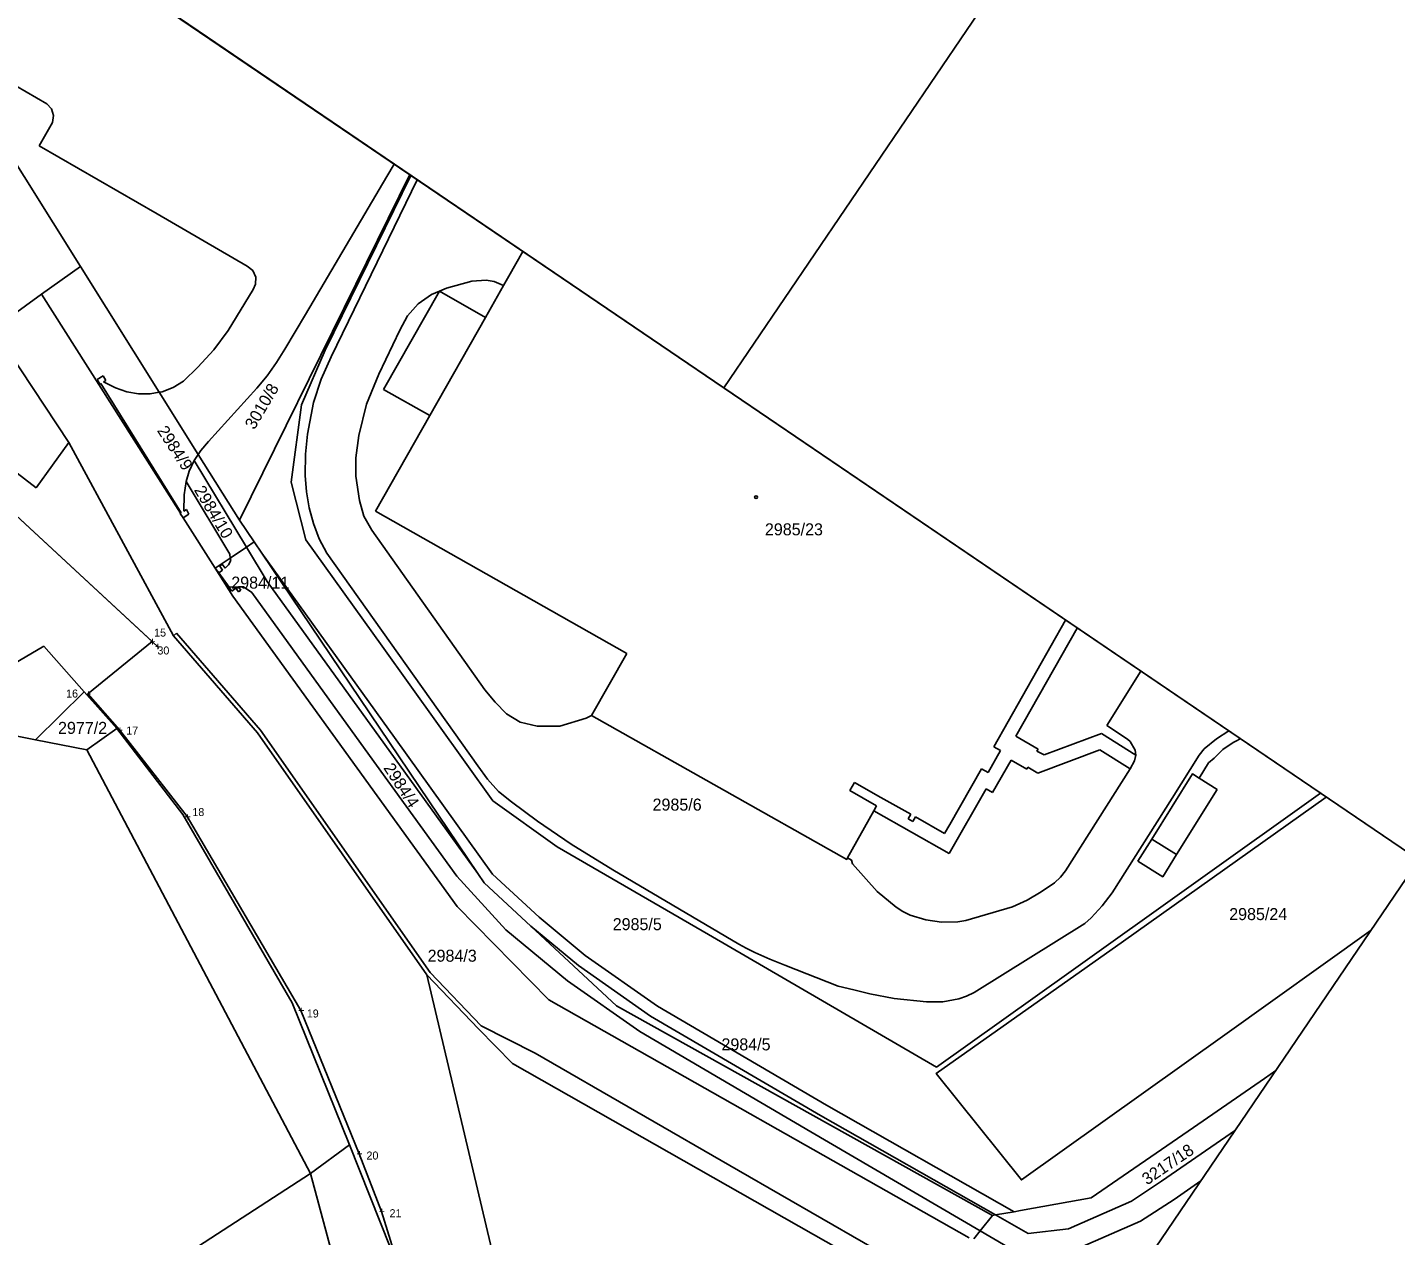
# Model space of a CAD drawing. Extents: x -620450 to -619936, y -1122925 to -1122443.
# Drawn here: x -620193.1 to -620022.1, y -1122848.8 to -1122697.8 of the extents above; entities that cross this region are included whole.
import ezdxf

# ---------------------------------------------------------------- set-up
doc = ezdxf.new("R2010")
doc.units = 0
for name, color, linetype in [('060603_ROZVODY_NN', 7, 'Continuous'), ('BODY', 7, 'Continuous'), ('BODY POPIS', 7, 'Continuous'), ('RÁMY', 7, 'Continuous'), ('UZEMNĚNÍ', 7, 'Continuous'), ('Vrstva 53', 7, 'Continuous'), ('Vrstva 55', 7, 'Continuous'), ('Vrstva 56', 7, 'Continuous'), ('Vrstva 57', 7, 'Continuous')]:
    doc.layers.add(name, color=color, linetype=linetype)

msp = doc.modelspace()

# ---------------------------------------------------------------- linework, layer by layer
at = {"layer": '060603_ROZVODY_NN'}
msp.add_lwpolyline([(-620240.17, -1122718.34), (-620228.34, -1122728.07), (-620221.17, -1122735.76), (-620213.63, -1122742.04), (-620205.95, -1122748.19), (-620177.51, -1122774.52), (-620185.52, -1122781.05), (-620181.59, -1122785.57), (-620173.13, -1122796.4), (-620158.91, -1122820.61), (-620151.64, -1122838.53), (-620148.85, -1122845.74), (-620146.97, -1122851.79), (-620142.65, -1122873.56), (-620132.31, -1122871.72), (-620130.54, -1122883.68), (-620130.19, -1122888.41), (-620130.04, -1122888.39)], dxfattribs=at)
at = {"layer": 'RÁMY'}
for points in [[(-620109.51, -1122560.98), (-620022.64, -1122619.97), (-620106.07, -1122742.82), (-620192.94, -1122683.83)], [(-620366.66, -1122565.85), (-620019.21, -1122801.81), (-620102.64, -1122924.66), (-620450.09, -1122688.7)], [(-620022.64, -1122619.97), (-619935.78, -1122678.97), (-620019.21, -1122801.81), (-620106.07, -1122742.82)], [(-620279.8, -1122624.84), (-620019.21, -1122801.81), (-620102.64, -1122924.66), (-620363.23, -1122747.69)]]:
    msp.add_lwpolyline(points, close=True, dxfattribs=at)
at = {"layer": 'UZEMNĚNÍ'}
msp.add_lwpolyline([(-620221.75, -1122750.37), (-620214.46, -1122741.38), (-620205.95, -1122748.19), (-620176.84, -1122775.14)], dxfattribs=at)
at = {"layer": 'Vrstva 53'}
for p, q in [((-620197.33, -1122735.44), (-620187.9, -1122749.66)), ((-620187.9, -1122749.66), (-620174.83, -1122773.82)), ((-620191.03, -1122775.11), (-620198.25, -1122779.35)), ((-620185.98, -1122780.81), (-620191.03, -1122775.11)), ((-620174.83, -1122773.82), (-620164.34, -1122785.91)), ((-620185.98, -1122780.81), (-620181.92, -1122785.4)), ((-620173.68, -1122796.12), (-620181.92, -1122785.4)), ((-620164.34, -1122785.91), (-620143.18, -1122816.17)), ((-620159.98, -1122819.68), (-620173.68, -1122796.12)), ((-620143.18, -1122816.17), (-620134.66, -1122852.11)), ((-620152.84, -1122837.4), (-620159.98, -1122819.68)), ((-620147.76, -1122850.22), (-620152.84, -1122837.4))]:
    msp.add_line(p, q, dxfattribs=at)
at = {"layer": 'Vrstva 55'}
for p, q in [((-620202.54, -1122702), (-620186.47, -1122727.64)), ((-620190.67, -1122707.32), (-620195.84, -1122704.31)), ((-620190.09, -1122707.94), (-620190.67, -1122707.32)), ((-620189.82, -1122708.78), (-620190.09, -1122707.94)), ((-620191.6, -1122712.59), (-620189.94, -1122709.65)), ((-620189.94, -1122709.65), (-620189.82, -1122708.78)), ((-620176.88, -1122721.09), (-620191.6, -1122712.59)), ((-620147.27, -1122714.85), (-620148.19, -1122716.42)), ((-620148.19, -1122716.42), (-620158.35, -1122733.67)), ((-620155.87, -1122738.11), (-620145.18, -1122716.27)), ((-620152.03, -1122729.88), (-620145.31, -1122716.18)), ((-620165.63, -1122727.6), (-620176.88, -1122721.09)), ((-620132.92, -1122728.86), (-620131.17, -1122725.78)), ((-620186.47, -1122727.64), (-620191.31, -1122731.11)), ((-620186.47, -1122727.64), (-620176.62, -1122743.36)), ((-620164.91, -1122728.17), (-620165.63, -1122727.6)), ((-620164.53, -1122728.99), (-620164.91, -1122728.17)), ((-620164.6, -1122729.87), (-620164.53, -1122728.99)), ((-620133.58, -1122730.02), (-620132.92, -1122728.86)), ((-620167.98, -1122735.66), (-620164.86, -1122730.54)), ((-620152.03, -1122729.88), (-620166.6, -1122759.34)), ((-620164.86, -1122730.54), (-620164.6, -1122729.87)), ((-620148.58, -1122743.04), (-620141.6, -1122730.74)), ((-620141.6, -1122730.74), (-620135.85, -1122734.02)), ((-620135.85, -1122734.02), (-620133.58, -1122730.02)), ((-620191.31, -1122731.11), (-620197.33, -1122735.44)), ((-620158.35, -1122733.67), (-620160.91, -1122737.97)), ((-620187.9, -1122749.66), (-620197.33, -1122735.44)), ((-620169.77, -1122738.05), (-620167.98, -1122735.66)), ((-620171.8, -1122740.25), (-620169.77, -1122738.05)), ((-620160.91, -1122737.97), (-620161.97, -1122739.66)), ((-620158.82, -1122744.94), (-620155.87, -1122738.11)), ((-620173.6, -1122742), (-620171.8, -1122740.25)), ((-620161.97, -1122739.66), (-620163.14, -1122741.3)), ((-620183.63, -1122741.31), (-620184.39, -1122741.79)), ((-620184.39, -1122741.79), (-620184.05, -1122742.35)), ((-620184.05, -1122742.35), (-620183.92, -1122742.28)), ((-620183.92, -1122742.28), (-620173.87, -1122758.44)), ((-620183.27, -1122741.89), (-620183.63, -1122741.31)), ((-620183.57, -1122742.07), (-620183.27, -1122741.89)), ((-620182.08, -1122742.82), (-620183.57, -1122742.07)), ((-620174.86, -1122742.79), (-620173.6, -1122742)), ((-620163.14, -1122741.3), (-620164.41, -1122742.85)), ((-620180.68, -1122743.31), (-620182.08, -1122742.82)), ((-620179.21, -1122743.55), (-620180.68, -1122743.31)), ((-620177.73, -1122743.55), (-620179.21, -1122743.55)), ((-620176.62, -1122743.36), (-620177.73, -1122743.55)), ((-620176.62, -1122743.36), (-620176.26, -1122743.3)), ((-620176.62, -1122743.36), (-620171.74, -1122751.13)), ((-620176.26, -1122743.3), (-620174.86, -1122742.79)), ((-620164.41, -1122742.85), (-620170.46, -1122749.51)), ((-620142.8, -1122746.27), (-620148.58, -1122743.04)), ((-620160.13, -1122754.62), (-620158.82, -1122744.94)), ((-620149.58, -1122758.23), (-620142.8, -1122746.27)), ((-620170.46, -1122749.51), (-620171.42, -1122750.65)), ((-620174.83, -1122773.82), (-620187.9, -1122749.66)), ((-620172.25, -1122751.89), (-620171.74, -1122751.13)), ((-620171.42, -1122750.65), (-620171.74, -1122751.13)), ((-620171.74, -1122751.13), (-620166.6, -1122759.34)), ((-620172.87, -1122753.23), (-620172.25, -1122751.89)), ((-620173.48, -1122756.2), (-620173.24, -1122754.52)), ((-620173.24, -1122754.52), (-620172.87, -1122753.23)), ((-620173.24, -1122754.52), (-620167.81, -1122763.6)), ((-620158.3, -1122761.8), (-620160.13, -1122754.62)), ((-620173.53, -1122758.23), (-620173.48, -1122756.2)), ((-620173.22, -1122758.03), (-620173.53, -1122758.23)), ((-620172.91, -1122758.59), (-620173.22, -1122758.03)), ((-620173.96, -1122758.5), (-620174, -1122758.53)), ((-620174, -1122758.53), (-620173.64, -1122759.08)), ((-620173.87, -1122758.44), (-620173.96, -1122758.5)), ((-620173.64, -1122759.08), (-620173.61, -1122759.06)), ((-620173.61, -1122759.06), (-620172.91, -1122758.59)), ((-620166.6, -1122759.34), (-620164.75, -1122762.08)), ((-620118.17, -1122776.02), (-620149.58, -1122758.23)), ((-620165.7, -1122762.73), (-620167.73, -1122764.1)), ((-620164.75, -1122762.08), (-620165.7, -1122762.73)), ((-620164.75, -1122762.08), (-620163.81, -1122763.48)), ((-620148.77, -1122775.1), (-620158.3, -1122761.8)), ((-620167.73, -1122764.1), (-620169.61, -1122765.37)), ((-620167.81, -1122763.6), (-620167.73, -1122764.1)), ((-620163.81, -1122763.48), (-620136.79, -1122803.52)), ((-620147.22, -1122786.5), (-620163.81, -1122763.48)), ((-620169.61, -1122765.37), (-620169.18, -1122765.95)), ((-620169.18, -1122765.95), (-620167.55, -1122768.23)), ((-620169.18, -1122765.95), (-620167.86, -1122767.72)), ((-620167.86, -1122767.72), (-620166.7, -1122767.69)), ((-620167.55, -1122768.23), (-620167.06, -1122767.87)), ((-620167.06, -1122767.87), (-620166.72, -1122768.33)), ((-620166.72, -1122768.33), (-620166.41, -1122768.09)), ((-620166.7, -1122767.69), (-620166.09, -1122767.67)), ((-620166.41, -1122768.09), (-620166.7, -1122767.69)), ((-620166.09, -1122767.67), (-620165.02, -1122768.39)), ((-620165.02, -1122768.39), (-620150.35, -1122788.75)), ((-620063.36, -1122771.83), (-620072.31, -1122787.67)), ((-620198.25, -1122779.35), (-620191.03, -1122775.11)), ((-620191.03, -1122775.11), (-620185.98, -1122780.81)), ((-620164.34, -1122785.91), (-620174.83, -1122773.82)), ((-620134.93, -1122794.41), (-620148.77, -1122775.1)), ((-620118.17, -1122776.02), (-620122.58, -1122783.75)), ((-620192.09, -1122786.79), (-620185.98, -1122780.81)), ((-620185.98, -1122780.81), (-620181.92, -1122785.4)), ((-620192.09, -1122786.79), (-620201.6, -1122784.9)), ((-620181.92, -1122785.4), (-620185.65, -1122788.07)), ((-620181.92, -1122785.4), (-620173.68, -1122796.12)), ((-620185.65, -1122788.07), (-620192.09, -1122786.79)), ((-620143.18, -1122816.17), (-620164.34, -1122785.91)), ((-620134.98, -1122803.58), (-620147.22, -1122786.5)), ((-620150.35, -1122788.75), (-620139.43, -1122803.84)), ((-620071.46, -1122788.15), (-620073.02, -1122790.9)), ((-620072.31, -1122787.67), (-620071.46, -1122788.15)), ((-620073.87, -1122790.42), (-620077.82, -1122797.38)), ((-620073.02, -1122790.9), (-620073.87, -1122790.42)), ((-620086.43, -1122793.99), (-620089.73, -1122792.12)), ((-620082.68, -1122796.11), (-620086.43, -1122793.99)), ((-620031.49, -1122793.48), (-620062.93, -1122815.9)), ((-620056.1, -1122811.95), (-620030.77, -1122793.96)), ((-620126.88, -1122800.18), (-620134.93, -1122794.41)), ((-620090.59, -1122801.55), (-620087.3, -1122795.66)), ((-620087.3, -1122795.66), (-620086.96, -1122795.04)), ((-620173.68, -1122796.12), (-620159.98, -1122819.68)), ((-620083.01, -1122796.68), (-620082.68, -1122796.11)), ((-620082.45, -1122797), (-620083.01, -1122796.68)), ((-620082.12, -1122796.42), (-620082.45, -1122797)), ((-620078.46, -1122798.5), (-620082.12, -1122796.42)), ((-620077.82, -1122797.38), (-620078.46, -1122798.5)), ((-620107.97, -1122811.15), (-620126.88, -1122800.18)), ((-620139.43, -1122803.84), (-620133.3, -1122810.53)), ((-620136.79, -1122803.52), (-620136, -1122804.68)), ((-620129.15, -1122808.98), (-620134.98, -1122803.58)), ((-620136, -1122804.68), (-620130.17, -1122810.08)), ((-620129.15, -1122808.98), (-620123.37, -1122813.77)), ((-620133.3, -1122810.53), (-620125.58, -1122816.92)), ((-620130.17, -1122810.08), (-620119.48, -1122820.03)), ((-620025.17, -1122810.59), (-620043.43, -1122823.66)), ((-620079.47, -1122827.69), (-620107.97, -1122811.15)), ((-620123.37, -1122813.77), (-620114.36, -1122820.1)), ((-620136.72, -1122822.9), (-620143.18, -1122816.17)), ((-620134.66, -1122852.11), (-620143.18, -1122816.17)), ((-620062.93, -1122815.9), (-620079.47, -1122827.69)), ((-620125.58, -1122816.92), (-620116.57, -1122823.25)), ((-620159.98, -1122819.68), (-620152.84, -1122837.4)), ((-620119.48, -1122820.03), (-620072.47, -1122846.25)), ((-620114.36, -1122820.1), (-620093.24, -1122832.45)), ((-620132.47, -1122827.27), (-620136.72, -1122822.9)), ((-620116.57, -1122823.25), (-620095.17, -1122835.78)), ((-620080.86, -1122856.55), (-620132.47, -1122827.27)), ((-620038.5, -1122829.12), (-620037.09, -1122828.14)), ((-620047.37, -1122835.25), (-620038.5, -1122829.12)), ((-620069.79, -1122845.77), (-620093.24, -1122832.45)), ((-620095.17, -1122835.78), (-620074.02, -1122848.16)), ((-620060.13, -1122844.05), (-620047.37, -1122835.25)), ((-620152.84, -1122837.4), (-620157.72, -1122840.99)), ((-620152.84, -1122837.4), (-620147.76, -1122850.22)), ((-620157.72, -1122840.99), (-620192.57, -1122863.59)), ((-620049.77, -1122844.23), (-620046.45, -1122841.92)), ((-620068.97, -1122845.62), (-620060.13, -1122844.05)), ((-620053.99, -1122846.97), (-620049.77, -1122844.23)), ((-620072.47, -1122846.25), (-620074.02, -1122848.16)), ((-620072.47, -1122846.25), (-620072.09, -1122846.18)), ((-620072.09, -1122846.18), (-620069.79, -1122845.77)), ((-620069.79, -1122845.77), (-620068.97, -1122845.62)), ((-620061.9, -1122850.43), (-620053.99, -1122846.97)), ((-620074.02, -1122848.16), (-620074.83, -1122849.15)), ((-620074.02, -1122848.16), (-620069.41, -1122850.86))]:
    msp.add_line(p, q, dxfattribs=at)
for points in [[(-620122.58, -1122783.75), (-620090.7, -1122801.75), (-620090.59, -1122801.55)], [(-620086.96, -1122795.04), (-620090.3, -1122793.12), (-620089.73, -1122792.12)], [(-620056.1, -1122811.95), (-620079.53, -1122828.52), (-620068.86, -1122841.8), (-620043.43, -1122823.66)]]:
    msp.add_lwpolyline(points, dxfattribs=at)
at = {"layer": 'Vrstva 56'}
for p, q in [((-620144.36, -1122716.82), (-620155.13, -1122738.93)), ((-620142.59, -1122731.16), (-620141.6, -1122730.74)), ((-620141.6, -1122730.74), (-620140.72, -1122730.36)), ((-620140.72, -1122730.36), (-620137.55, -1122729.49)), ((-620137.55, -1122729.49), (-620135.75, -1122729.37)), ((-620135.75, -1122729.37), (-620134.75, -1122729.52)), ((-620134.75, -1122729.52), (-620133.58, -1122730.02)), ((-620191.31, -1122731.11), (-620173.96, -1122758.5)), ((-620145.58, -1122733.83), (-620144.26, -1122732.31)), ((-620144.26, -1122732.31), (-620142.59, -1122731.16)), ((-620146.56, -1122735.6), (-620145.58, -1122733.83)), ((-620142.8, -1122746.27), (-620135.85, -1122734.02)), ((-620149.15, -1122741.1), (-620146.56, -1122735.6)), ((-620156.36, -1122741.72), (-620155.13, -1122738.93)), ((-620157.32, -1122744.66), (-620156.36, -1122741.72)), ((-620150.71, -1122744.84), (-620149.15, -1122741.1)), ((-620205.48, -1122744.93), (-620191.99, -1122755.33)), ((-620158.07, -1122748.62), (-620157.32, -1122744.66)), ((-620151.67, -1122748.77), (-620150.71, -1122744.84)), ((-620158.33, -1122751.09), (-620158.07, -1122748.62)), ((-620152.03, -1122751.56), (-620151.67, -1122748.77)), ((-620191.99, -1122755.33), (-620187.9, -1122749.66)), ((-620158.37, -1122753.78), (-620158.33, -1122751.09)), ((-620172.25, -1122751.89), (-620165.7, -1122762.73)), ((-620152.03, -1122753.86), (-620152.03, -1122751.56)), ((-620158.2, -1122755.8), (-620158.37, -1122753.78)), ((-620151.58, -1122756.91), (-620152.03, -1122753.86)), ((-620157.86, -1122757.82), (-620158.2, -1122755.8)), ((-620157.34, -1122759.76), (-620157.86, -1122757.82)), ((-620151.04, -1122758.86), (-620151.58, -1122756.91)), ((-620173.61, -1122759.06), (-620169.61, -1122765.37)), ((-620156.64, -1122761.69), (-620157.34, -1122759.76)), ((-620150.03, -1122760.6), (-620151.04, -1122758.86)), ((-620135.93, -1122780.56), (-620150.03, -1122760.6)), ((-620165.7, -1122762.73), (-620163.11, -1122767.02)), ((-620155.67, -1122763.48), (-620156.64, -1122761.69)), ((-620168.75, -1122764.87), (-620169.05, -1122765.1)), ((-620168.38, -1122765.37), (-620168.75, -1122764.87)), ((-620167.95, -1122764.93), (-620168.38, -1122765.37)), ((-620167.68, -1122764.39), (-620167.95, -1122764.93)), ((-620167.73, -1122764.1), (-620167.68, -1122764.39)), ((-620136.78, -1122790.07), (-620155.67, -1122763.48)), ((-620169.61, -1122765.37), (-620167.41, -1122768.84)), ((-620168.7, -1122765.62), (-620169.18, -1122765.95)), ((-620169.05, -1122765.1), (-620168.7, -1122765.62)), ((-620163.11, -1122767.02), (-620148.44, -1122787.38)), ((-620167.41, -1122768.84), (-620139.39, -1122807.63)), ((-620174.83, -1122773.82), (-620174.45, -1122773.49)), ((-620174.45, -1122773.49), (-620163.96, -1122785.58)), ((-620061.88, -1122772.83), (-620069.55, -1122786.35)), ((-620058.21, -1122785), (-620053.96, -1122778.22)), ((-620134.64, -1122782.1), (-620135.93, -1122780.56)), ((-620133.21, -1122783.55), (-620134.64, -1122782.1)), ((-620131.49, -1122784.61), (-620133.21, -1122783.55)), ((-620055.6, -1122786.71), (-620058.21, -1122785)), ((-620163.96, -1122785.58), (-620142.77, -1122815.89)), ((-620069.55, -1122786.35), (-620066.78, -1122787.99)), ((-620066.03, -1122788.67), (-620058.85, -1122786.02)), ((-620058.85, -1122786.02), (-620054.57, -1122788.73)), ((-620055.26, -1122787.03), (-620055.6, -1122786.71)), ((-620054.65, -1122788.11), (-620055.26, -1122787.03)), ((-620044.47, -1122786.69), (-620046.04, -1122787.93)), ((-620042.95, -1122785.69), (-620044.47, -1122786.69)), ((-620043.69, -1122788), (-620042.42, -1122787.14)), ((-620042.42, -1122787.14), (-620041.98, -1122786.91)), ((-620041.98, -1122786.91), (-620041.52, -1122786.66)), ((-620185.65, -1122788.07), (-620157.72, -1122840.99)), ((-620148.44, -1122787.38), (-620136.79, -1122803.52)), ((-620066.78, -1122787.99), (-620066.95, -1122788.23)), ((-620066.95, -1122788.23), (-620066.03, -1122788.67)), ((-620059.07, -1122788.06), (-620066.82, -1122790.95)), ((-620055.29, -1122790.43), (-620059.07, -1122788.06)), ((-620054.57, -1122788.73), (-620054.73, -1122789.43)), ((-620054.57, -1122788.73), (-620054.65, -1122788.11)), ((-620046.66, -1122788.71), (-620050.01, -1122794.09)), ((-620046.04, -1122787.93), (-620046.66, -1122788.71)), ((-620044.78, -1122789.08), (-620043.69, -1122788)), ((-620135.58, -1122791.72), (-620136.78, -1122790.07)), ((-620070.13, -1122789.33), (-620072.48, -1122793.37)), ((-620068.2, -1122790.46), (-620070.13, -1122789.33)), ((-620068.05, -1122790.2), (-620068.2, -1122790.46)), ((-620066.82, -1122790.95), (-620068.05, -1122790.2)), ((-620063.35, -1122803.17), (-620055.29, -1122790.43)), ((-620054.73, -1122789.43), (-620055.29, -1122790.43)), ((-620046.67, -1122791.59), (-620045.49, -1122789.69)), ((-620045.49, -1122789.69), (-620044.78, -1122789.08)), ((-620134.2, -1122793.25), (-620135.58, -1122791.72)), ((-620044.39, -1122793.03), (-620046.67, -1122791.59)), ((-620132.61, -1122794.57), (-620134.2, -1122793.25)), ((-620073.28, -1122792.94), (-620077.88, -1122800.99)), ((-620072.48, -1122793.37), (-620073.28, -1122792.94)), ((-620049.47, -1122801.15), (-620044.39, -1122793.03)), ((-620129.33, -1122796.98), (-620132.61, -1122794.57)), ((-620077.88, -1122800.99), (-620087.3, -1122795.66)), ((-620050.01, -1122794.09), (-620057.54, -1122805.91)), ((-620125.13, -1122799.85), (-620129.33, -1122796.98)), ((-620119.93, -1122803.03), (-620125.13, -1122799.85)), ((-620054.32, -1122801.97), (-620052.58, -1122799.22)), ((-620049.47, -1122801.15), (-620052.58, -1122799.22)), ((-620104.17, -1122812.35), (-620119.93, -1122803.03)), ((-620064.71, -1122804.67), (-620064, -1122803.96)), ((-620064, -1122803.96), (-620063.35, -1122803.17)), ((-620086.89, -1122805.77), (-620084.53, -1122807.72)), ((-620068.14, -1122806.82), (-620066.39, -1122805.81)), ((-620066.39, -1122805.81), (-620064.71, -1122804.67)), ((-620057.54, -1122805.91), (-620058.79, -1122807.53)), ((-620139.39, -1122807.63), (-620127.92, -1122819.29)), ((-620075.82, -1122809.38), (-620069.99, -1122807.67)), ((-620069.99, -1122807.67), (-620068.14, -1122806.82)), ((-620058.79, -1122807.53), (-620060.14, -1122809.05)), ((-620084.53, -1122807.72), (-620083.69, -1122808.26)), ((-620083.69, -1122808.26), (-620082.76, -1122808.7)), ((-620082.76, -1122808.7), (-620080.83, -1122809.28)), ((-620080.83, -1122809.28), (-620078.84, -1122809.59)), ((-620076.83, -1122809.56), (-620075.82, -1122809.38)), ((-620060.14, -1122809.05), (-620060.93, -1122809.75)), ((-620124.23, -1122815), (-620130.17, -1122810.08)), ((-620078.84, -1122809.59), (-620076.83, -1122809.56)), ((-620060.93, -1122809.75), (-620074.77, -1122818.38)), ((-620103.27, -1122812.85), (-620104.17, -1122812.35)), ((-620102.16, -1122813.38), (-620103.27, -1122812.85)), ((-620100.32, -1122814.22), (-620102.16, -1122813.38)), ((-620098.43, -1122814.97), (-620100.32, -1122814.22)), ((-620142.77, -1122815.89), (-620136.36, -1122822.55)), ((-620115.22, -1122821.33), (-620124.23, -1122815)), ((-620091.75, -1122817.59), (-620098.43, -1122814.97)), ((-620089.79, -1122818.03), (-620091.75, -1122817.59)), ((-620127.92, -1122819.29), (-620075.39, -1122849.03)), ((-620087.81, -1122818.54), (-620089.79, -1122818.03)), ((-620084.78, -1122819.14), (-620087.81, -1122818.54)), ((-620080.74, -1122819.56), (-620084.78, -1122819.14)), ((-620078.69, -1122819.55), (-620080.74, -1122819.56)), ((-620076.68, -1122819.17), (-620078.69, -1122819.55)), ((-620075.71, -1122818.84), (-620076.68, -1122819.17)), ((-620074.77, -1122818.38), (-620075.71, -1122818.84)), ((-620093.98, -1122833.75), (-620115.22, -1122821.33)), ((-620136.36, -1122822.55), (-620129.64, -1122825.94)), ((-620129.64, -1122825.94), (-620104.21, -1122840.64)), ((-620072.09, -1122846.18), (-620093.98, -1122833.75)), ((-620051.34, -1122841.97), (-620042.13, -1122835.56)), ((-620149.02, -1122872.99), (-620157.72, -1122840.99)), ((-620104.21, -1122840.64), (-620080.18, -1122854.43)), ((-620055.09, -1122844.45), (-620051.34, -1122841.97)), ((-620063, -1122847.91), (-620055.09, -1122844.45)), ((-620072.09, -1122846.18), (-620068.02, -1122848.49)), ((-620068.02, -1122848.49), (-620063, -1122847.91))]:
    msp.add_line(p, q, dxfattribs=at)
for points in [[(-620122.58, -1122783.75), (-620123.27, -1122784.1), (-620126.53, -1122785.08), (-620129.37, -1122785.1), (-620131.49, -1122784.61)], [(-620046.67, -1122791.59), (-620047.49, -1122791.07), (-620052.58, -1122799.22)], [(-620090.59, -1122801.55), (-620090.11, -1122801.83), (-620089.99, -1122802.28), (-620086.89, -1122805.77)], [(-620054.32, -1122801.97), (-620051.2, -1122803.92), (-620049.47, -1122801.15)]]:
    msp.add_lwpolyline(points, dxfattribs=at)
at = {"layer": 'Vrstva 57'}
msp.add_circle((-620102.03, -1122756.47), 0.175, dxfattribs=at)

# ---------------------------------------------------------------- texts
at = {"layer": 'BODY'}
for p in [(-620177.85, -1122775.02), (-620177.18, -1122775.64), (-620185.86, -1122781.55), (-620181.92, -1122786.07), (-620173.46, -1122796.9), (-620159.24, -1122821.11), (-620151.97, -1122839.03), (-620149.18, -1122846.24)]:
    msp.add_text('+', height=1, dxfattribs=at).set_placement(p)
at = {"layer": 'BODY POPIS'}
for s, p in [('15', (-620177.25, -1122773.9)), ('30', (-620176.84, -1122776.14)), ('16', (-620188.25, -1122781.52)), ('17', (-620180.73, -1122786.14)), ('18', (-620172.47, -1122796.33)), ('19', (-620158.17, -1122821.5)), ('20', (-620150.71, -1122839.25)), ('21', (-620147.83, -1122846.46))]:
    msp.add_text(s, height=1, dxfattribs=at).set_placement(p)
at = {"layer": 'Vrstva 57'}
for s, rotation, p in [('3010/8', 59.4683, (-620164.72, -1122748.13)), ('2984/9', 303.103, (-620176.94, -1122748.16)), ('2984/10', 300.8806, (-620172.31, -1122755.59)), ('2984/4', 303.3, (-620148.65, -1122790.32)), ('3217/18', 34.2, (-620053.16, -1122842.5))]:
    msp.add_text(s, height=1.5, rotation=rotation, dxfattribs=at).set_placement(p)
for s, p in [('2985/23', (-620100.92, -1122761.25)), ('2984/11', (-620167.61, -1122767.91)), ('2977/2', (-620189.26, -1122786.06)), ('2985/6', (-620114.96, -1122795.65)), ('2985/5', (-620119.94, -1122810.59)), ('2985/24', (-620042.9, -1122809.33)), ('2984/3', (-620143.07, -1122814.53)), ('2984/5', (-620106.35, -1122825.61))]:
    msp.add_text(s, height=1.5, dxfattribs=at).set_placement(p)

doc.saveas('drawing.dxf')
